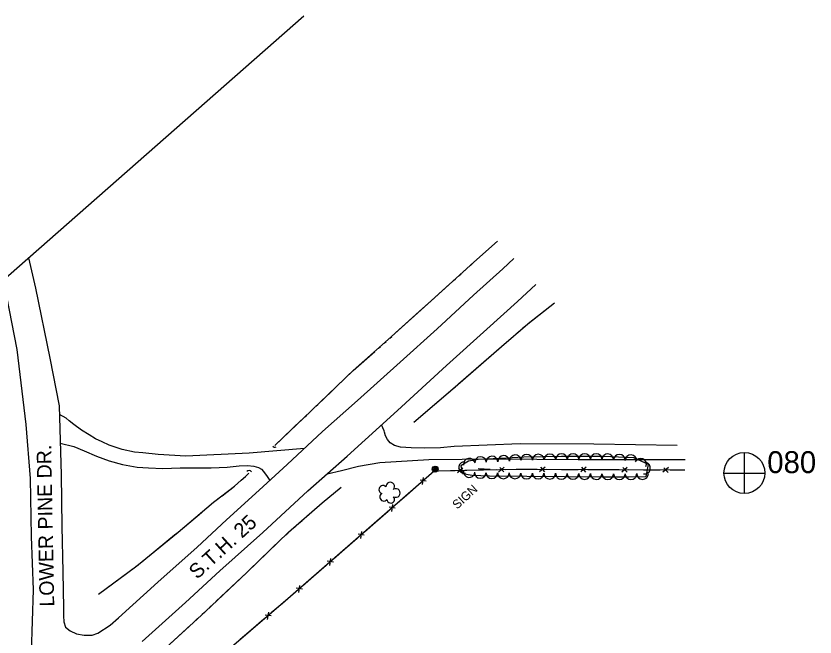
# Model space of a CAD drawing. Extents: x 295302 to 297577, y 27143 to 29590.
# Drawn here: x 296296 to 296843, y 28612 to 29036 of the extents above; entities that cross this region are included whole.
import ezdxf

# ---------------------------------------------------------------- set-up
doc = ezdxf.new("R2010")
doc.units = 0
for name, color, linetype in [('Level 11', 7, 'Continuous'), ('Level 14', 7, 'Continuous'), ('Level 15', 7, 'Continuous'), ('Level 17', 7, 'Continuous'), ('Level 18', 7, 'Continuous'), ('Level 19', 7, 'Continuous'), ('Level 4', 7, 'Continuous')]:
    doc.layers.add(name, color=color, linetype=linetype)

msp = doc.modelspace()

# ---------------------------------------------------------------- linework, layer by layer
at = {"layer": 'Level 11'}
for points in [[(296304.47, 28870.9), (296309.1, 28850.24), (296318.9, 28802.39), (296325.34, 28769.85), (296326.62, 28722.58), (296327.24, 28687.32), (296327.84, 28656.36), (296328.27, 28631.46), (296328.25, 28626.21), (296328.56, 28621.99), (296329.74, 28618.52), (296332.79, 28615.94), (296337.17, 28613.95), (296342.37, 28612.88), (296348.04, 28612.92), (296351.83, 28614.36), (296360.25, 28619.75), (296366, 28624.9), (296392.93, 28649.29), (296419.71, 28673.23), (296439.8, 28691.72), (296462.23, 28712), (296481.48, 28729.56), (296505.53, 28752.19), (296529.53, 28773.36), (296558.85, 28799.68), (296584.03, 28822.49), (296609.02, 28845.42), (296629.06, 28863.43), (296636.52, 28870.53)], [(296382.14, 28608.65), (296411.83, 28635.34), (296435.41, 28656.9), (296464.65, 28683.24), (296495.65, 28711.67), (296522.59, 28735.4), (296556.86, 28766.68), (296590.55, 28797.27), (296618.12, 28822.28), (296639.04, 28841.17), (296651.56, 28852.78)], [(296294.87, 28559.97), (296297.65, 28563.85), (296299.73, 28567.96), (296302.82, 28577.65), (296305.56, 28590.72), (296306.48, 28601.01), (296307.72, 28644.03), (296306.49, 28680.46), (296305.66, 28720), (296302.68, 28756.98), (296296.5, 28808.21), (296289.55, 28844.57)]]:
    msp.add_lwpolyline(points, dxfattribs=at)
at = {"layer": 'Level 14'}
msp.add_line((296612.08, 28726.91), (296620.47, 28726.38), dxfattribs=at)
for centre, radius in [((296582.75, 28726.52), 2.02), ((296582.74, 28726.52), 1.52), ((296582.77, 28726.5), 1.01), ((296582.76, 28726.51), 0.502)]:
    msp.add_circle(centre, radius, dxfattribs=at)
at = {"layer": 'Level 15'}
for p, q in [((296601.76, 28727.2), (296598.08, 28723.85)), ((296601.66, 28723.93), (296598.77, 28727.07)), ((296629.86, 28727.8), (296626.18, 28724.46)), ((296629.76, 28724.53), (296626.87, 28727.67)), ((296658, 28727.9), (296654.24, 28724.65)), ((296657.82, 28724.64), (296655.01, 28727.85)), ((296686.11, 28727.78), (296682.35, 28724.53)), ((296685.92, 28724.52), (296683.12, 28727.73)), ((296714.21, 28727.67), (296710.45, 28724.41)), ((296714.03, 28724.4), (296711.22, 28727.61)), ((296742.32, 28727.55), (296738.55, 28724.3)), ((296742.13, 28724.28), (296739.33, 28727.49)), ((296574.6, 28720.86), (296573.92, 28715.93)), ((296576.61, 28718.28), (296572.39, 28718.84)), ((296555.42, 28699.82), (296551.2, 28700.38)), ((296553.41, 28702.4), (296552.73, 28697.47)), ((296534.23, 28681.36), (296530.01, 28681.92)), ((296532.22, 28683.93), (296531.54, 28679.01)), ((296511.03, 28665.47), (296510.35, 28660.54)), ((296513.04, 28662.9), (296508.82, 28663.45)), ((296491.86, 28644.43), (296487.63, 28644.99)), ((296489.84, 28647.01), (296489.16, 28642.08)), ((296470.53, 28626.1), (296466.31, 28626.71)), ((296468.54, 28628.7), (296467.81, 28623.78))]:
    msp.add_line(p, q, dxfattribs=at)
for points in [[(296753.53, 28725.75), (296638.27, 28726.23), (296582.04, 28725.02), (296483.74, 28639.37), (296430.45, 28593.88), (296380.25, 28550.33), (296347.72, 28524.4), (296346.66, 28496.83), (296346.69, 28414.92), (296346.93, 28341.84), (296346.38, 28287.27), (296346.53, 28219.91), (296346.37, 28154.48), (296346.77, 28115.78), (296346.81, 28104.59)], [(296584.91, 28725.08), (296582.04, 28725.02), (296576.63, 28720.31)], [(296596.33, 28725.33), (296584.91, 28725.08)], [(296613.01, 28725.69), (296602.97, 28725.47)], [(296624.43, 28725.93), (296613.01, 28725.69)], [(296641.11, 28726.22), (296638.27, 28726.23), (296631.06, 28726.08)], [(296652.53, 28726.17), (296641.11, 28726.22)], [(296669.21, 28726.1), (296659.17, 28726.14)], [(296680.63, 28726.05), (296669.21, 28726.1)], [(296697.32, 28725.98), (296687.27, 28726.02)], [(296708.74, 28725.93), (296697.32, 28725.98)], [(296725.42, 28725.86), (296715.38, 28725.91)], [(296736.84, 28725.82), (296725.42, 28725.86)], [(296753.53, 28725.75), (296743.48, 28725.79)], [(296571.62, 28715.94), (296563.02, 28708.44)], [(296563.02, 28708.44), (296555.44, 28701.84)], [(296550.44, 28697.48), (296541.83, 28689.98)], [(296541.83, 28689.98), (296534.25, 28683.38)], [(296529.25, 28679.02), (296520.64, 28671.52)], [(296520.64, 28671.52), (296513.06, 28664.92)], [(296508.06, 28660.56), (296499.45, 28653.05)], [(296499.45, 28653.05), (296491.87, 28646.45)], [(296486.87, 28642.09), (296483.74, 28639.37), (296478.21, 28634.65)], [(296478.21, 28634.65), (296470.57, 28628.12)], [(296465.52, 28623.82), (296456.83, 28616.4)], [(296456.83, 28616.4), (296449.19, 28609.88)]]:
    msp.add_lwpolyline(points, dxfattribs=at)
for centre, radius, start, end in [((296472.95, 28742.96), 1.49, 199.5872, 305.8268), ((296455.35, 28723.58), 1.99, 33.3278, 139.5674)]:
    msp.add_arc(centre, radius, start, end, dxfattribs=at)
at = {"layer": 'Level 17'}
for points in [[(296493.3, 28740.68), (296455.5, 28737.41), (296412.14, 28735.24), (296393.21, 28736.49), (296382.61, 28737.52), (296377.02, 28738.12), (296368.43, 28739.83), (296359.61, 28742.85), (296354.75, 28745.22), (296350.33, 28747.26), (296345.88, 28749.94), (296340.62, 28753.05), (296335.36, 28757), (296332.21, 28759.53), (296330.13, 28761.4), (296325.5, 28763.78)], [(296748.35, 28742.76), (296691.25, 28743.52), (296640.96, 28743.82), (296595.75, 28742.06), (296586.34, 28741.15), (296575.09, 28740.86), (296566.29, 28741.09), (296559.03, 28741.62), (296554.95, 28742.66), (296551.95, 28744.57), (296550.14, 28746.71), (296548.73, 28749.31), (296547.96, 28751.68), (296547.73, 28752.67), (296545.97, 28756.73)], [(296326.03, 28744.3), (296335.4, 28742.06), (296342.52, 28739.1), (296350.99, 28735.4), (296359.54, 28732.17), (296368.81, 28729.57), (296378.86, 28727.87), (296386.57, 28727.34), (296396.34, 28726.91), (296408.23, 28727.43), (296420.41, 28727.33), (296429.41, 28727.28), (296440.26, 28727.78), (296448.51, 28728.65), (296454.31, 28728.91), (296458.58, 28728.41), (296461.81, 28727.65), (296463.76, 28726.49), (296465.31, 28724.82), (296466.45, 28723.19), (296467.18, 28722.15), (296467.72, 28721.35), (296469.57, 28718.69)], [(296508.72, 28723.18), (296518.68, 28725.63), (296530.33, 28728.57), (296544.8, 28730.94), (296578.37, 28733.05), (296624.09, 28733.53), (296680.5, 28733.17), (296728.6, 28733.01), (296753.87, 28733)]]:
    msp.add_lwpolyline(points, dxfattribs=at)
at = {"layer": 'Level 18'}
msp.add_lwpolyline([(296696.89, 28721.28), (296715.34, 28721.31), (296727.1, 28721.37), (296728.7, 28729.74), (296718.66, 28734.26), (296697.6, 28735.11), (296669.15, 28735.04), (296643.34, 28734.6), (296627.44, 28733.75), (296612.1, 28732.98), (296605.52, 28731.92), (296600.39, 28728.69), (296601.51, 28723.43), (296608.01, 28722.33), (296619.8, 28721.94), (296696.89, 28721.28)], dxfattribs=at)
for centre, radius, start, end in [((296621.67, 28731.38), 3.97, 2.8799, 182.8646), ((296629.61, 28731.79), 3.97, 3.0607, 183.0454), ((296637.54, 28732.21), 3.97, 3.0607, 183.0454), ((296645.39, 28732.56), 3.97, 0.9933, 180.978), ((296653.33, 28732.69), 3.97, 0.9933, 180.978), ((296661.27, 28732.83), 3.97, 0.9933, 180.978), ((296669.17, 28732.97), 3.97, 0.1466, 180.1313), ((296677.11, 28732.98), 3.97, 0.1466, 180.1313), ((296685.05, 28733), 3.97, 0.1466, 180.1313), ((296692.99, 28733.02), 3.97, 0.1466, 180.1313), ((296700.84, 28732.9), 3.97, 357.6946, 177.6792), ((296708.77, 28732.58), 3.97, 357.6946, 177.6792), ((296716.71, 28732.26), 3.97, 357.6946, 177.6792), ((296602.76, 28727.54), 3.97, 102.0258, 282.0105), ((296606.11, 28729.91), 3.97, 9.1516, 189.1363), ((296613.74, 28730.98), 3.97, 2.8799, 182.8646), ((296723.34, 28729.87), 3.97, 335.7248, 155.7095), ((296726.09, 28727.18), 3.97, 259.1844, 79.169), ((296605.97, 28724.78), 3.97, 170.4481, 350.4328), ((296613.6, 28724.22), 3.97, 178.098, 358.0827), ((296621.49, 28724), 3.97, 179.5186, 359.5033), ((296629.42, 28723.93), 3.97, 179.5186, 359.5033), ((296637.36, 28723.87), 3.97, 179.5186, 359.5033), ((296645.3, 28723.8), 3.97, 179.5186, 359.5033), ((296653.24, 28723.73), 3.97, 179.5186, 359.5033), ((296661.18, 28723.66), 3.97, 179.5186, 359.5033), ((296669.12, 28723.6), 3.97, 179.5186, 359.5033), ((296677.06, 28723.53), 3.97, 179.5186, 359.5033), ((296685, 28723.46), 3.97, 179.5186, 359.5033), ((296692.94, 28723.39), 3.97, 179.5186, 359.5033), ((296700.86, 28723.36), 3.97, 180.0946, 0.0793), ((296708.8, 28723.38), 3.97, 180.0946, 0.0793), ((296716.73, 28723.39), 3.97, 180.2856, 0.2702), ((296724.67, 28723.43), 3.97, 180.2856, 0.2702), ((296547.01, 28712.5), 2.78, 43.9105, 251.6835), ((296551.98, 28714.54), 2.97, 320.9396, 182.1735), ((296547.55, 28707.46), 2.78, 120.5875, 321.5986), ((296555.85, 28710.15), 2.97, 238.5904, 121.5637), ((296552.34, 28705.89), 2.61, 183.2957, 41.2283)]:
    msp.add_arc(centre, radius, start, end, dxfattribs=at)
at = {"layer": 'Level 19'}
for points in [[(296473, 28742.68), (296497.81, 28766.28), (296526.48, 28793.9), (296550.59, 28815.06), (296579.95, 28841.62), (296609.24, 28867.96), (296625.42, 28882.47)], [(296606.82, 28865.78), (296609.24, 28867.96), (296625.42, 28882.47)], [(296602.97, 28862.33), (296604.25, 28863.48)], [(296595.28, 28855.41), (296596.56, 28856.56)], [(296599.13, 28858.87), (296600.41, 28860.02)], [(296574.15, 28836.37), (296579.95, 28841.62), (296592.72, 28853.1)], [(296568.1, 28758.63), (296596.41, 28782.7), (296628.17, 28810.41), (296646.14, 28825.92), (296664.37, 28840.17)], [(296646.35, 28826.09), (296664.37, 28840.17)], [(296555.62, 28819.6), (296574.15, 28836.37)], [(296642.76, 28823), (296643.96, 28824.03)], [(296635.6, 28816.82), (296636.79, 28817.85)], [(296639.18, 28819.91), (296640.38, 28820.94)], [(296547.91, 28812.71), (296549.21, 28813.84)], [(296551.78, 28816.13), (296553.06, 28817.29)], [(296615.95, 28799.75), (296628.17, 28810.41), (296633.21, 28814.76)], [(296522.8, 28790.36), (296526.48, 28793.9), (296541.43, 28807.02)], [(296544.02, 28809.3), (296545.32, 28810.43)], [(296598.72, 28784.71), (296615.95, 28799.75)], [(296504.81, 28773.02), (296522.8, 28790.36)], [(296591.53, 28778.55), (296592.73, 28779.57)], [(296595.14, 28781.62), (296596.34, 28782.64)], [(296587.93, 28775.49), (296589.13, 28776.51)], [(296501.08, 28769.43), (296502.33, 28770.63)], [(296568.1, 28758.63), (296585.52, 28773.44)], [(296493.61, 28762.28), (296494.86, 28763.47)], [(296497.36, 28765.85), (296497.81, 28766.28), (296498.6, 28767.04)], [(296473, 28742.68), (296491.11, 28759.9)], [(296352.18, 28640.88), (296378.56, 28660.38), (296406.84, 28683.48), (296431.06, 28703.81), (296445.27, 28714.95), (296449.9, 28719), (296452.89, 28721.49), (296455.17, 28723.73)], [(296436.83, 28708.33), (296445.27, 28714.95), (296449.9, 28719), (296452.89, 28721.49), (296455.17, 28723.73)], [(296331.27, 28540.05), (296343.21, 28552.17), (296372.71, 28578.2), (296390.25, 28596.86), (296425.43, 28629.21), (296453.85, 28655.82), (296482.43, 28683.39), (296505.41, 28703.49), (296518.38, 28714.25)], [(296494.83, 28694.24), (296505.41, 28703.49), (296518.38, 28714.25)], [(296429.07, 28702.15), (296430.34, 28703.21)], [(296432.92, 28705.27), (296434.22, 28706.29)], [(296425.28, 28698.96), (296426.54, 28700.02)], [(296404.36, 28681.45), (296406.84, 28683.48), (296422.74, 28696.83)], [(296485.2, 28685.82), (296486.8, 28687.22)], [(296490.02, 28690.03), (296491.62, 28691.43)], [(296385.8, 28666.3), (296404.36, 28681.45)], [(296480.48, 28681.51), (296482.01, 28682.99)], [(296455.16, 28657.09), (296477.41, 28678.55)], [(296378.1, 28660.04), (296378.56, 28660.38), (296379.39, 28661.07)], [(296381.96, 28663.16), (296383.23, 28664.2)], [(296352.18, 28640.88), (296371.45, 28655.13)], [(296374.11, 28657.1), (296375.44, 28658.08)], [(296432.62, 28635.94), (296453.85, 28655.82), (296455.16, 28657.09)], [(296427.96, 28631.57), (296429.51, 28633.03)], [(296423.27, 28627.22), (296424.84, 28628.67)], [(296418.56, 28622.9), (296420.13, 28624.34)], [(296392.67, 28599.09), (296415.42, 28620.01)]]:
    msp.add_lwpolyline(points, dxfattribs=at)
at = {"layer": 'Level 4'}
for p, q in [((296794.33, 28737.85), (296794.27, 28710)), ((296780.42, 28723.82), (296808.33, 28723.81))]:
    msp.add_line(p, q, dxfattribs=at)
msp.add_lwpolyline([(295725.55, 28362.64), (296492.89, 29036.34)], dxfattribs=at)
msp.add_circle((296794.39, 28723.83), 14, dxfattribs=at)

# ---------------------------------------------------------------- texts
at = {"layer": 'Level 11'}
for s, rotation, p in [('LOWER PINE DR.', 91.1086, (296322.01, 28632.57)), ('S.T.H. 25', 42.4294, (296419.75, 28650.72))]:
    msp.add_text(s, height=10, rotation=rotation, dxfattribs=at).set_placement(p)
at = {"layer": 'Level 14'}
msp.add_text('SIGN', height=6, rotation=42.516, dxfattribs=at).set_placement((296597.83, 28698.77))
at = {"layer": 'Level 4'}
msp.add_text('080', height=15, dxfattribs=at).set_placement((296810.04, 28723.76))

doc.saveas('drawing.dxf')
